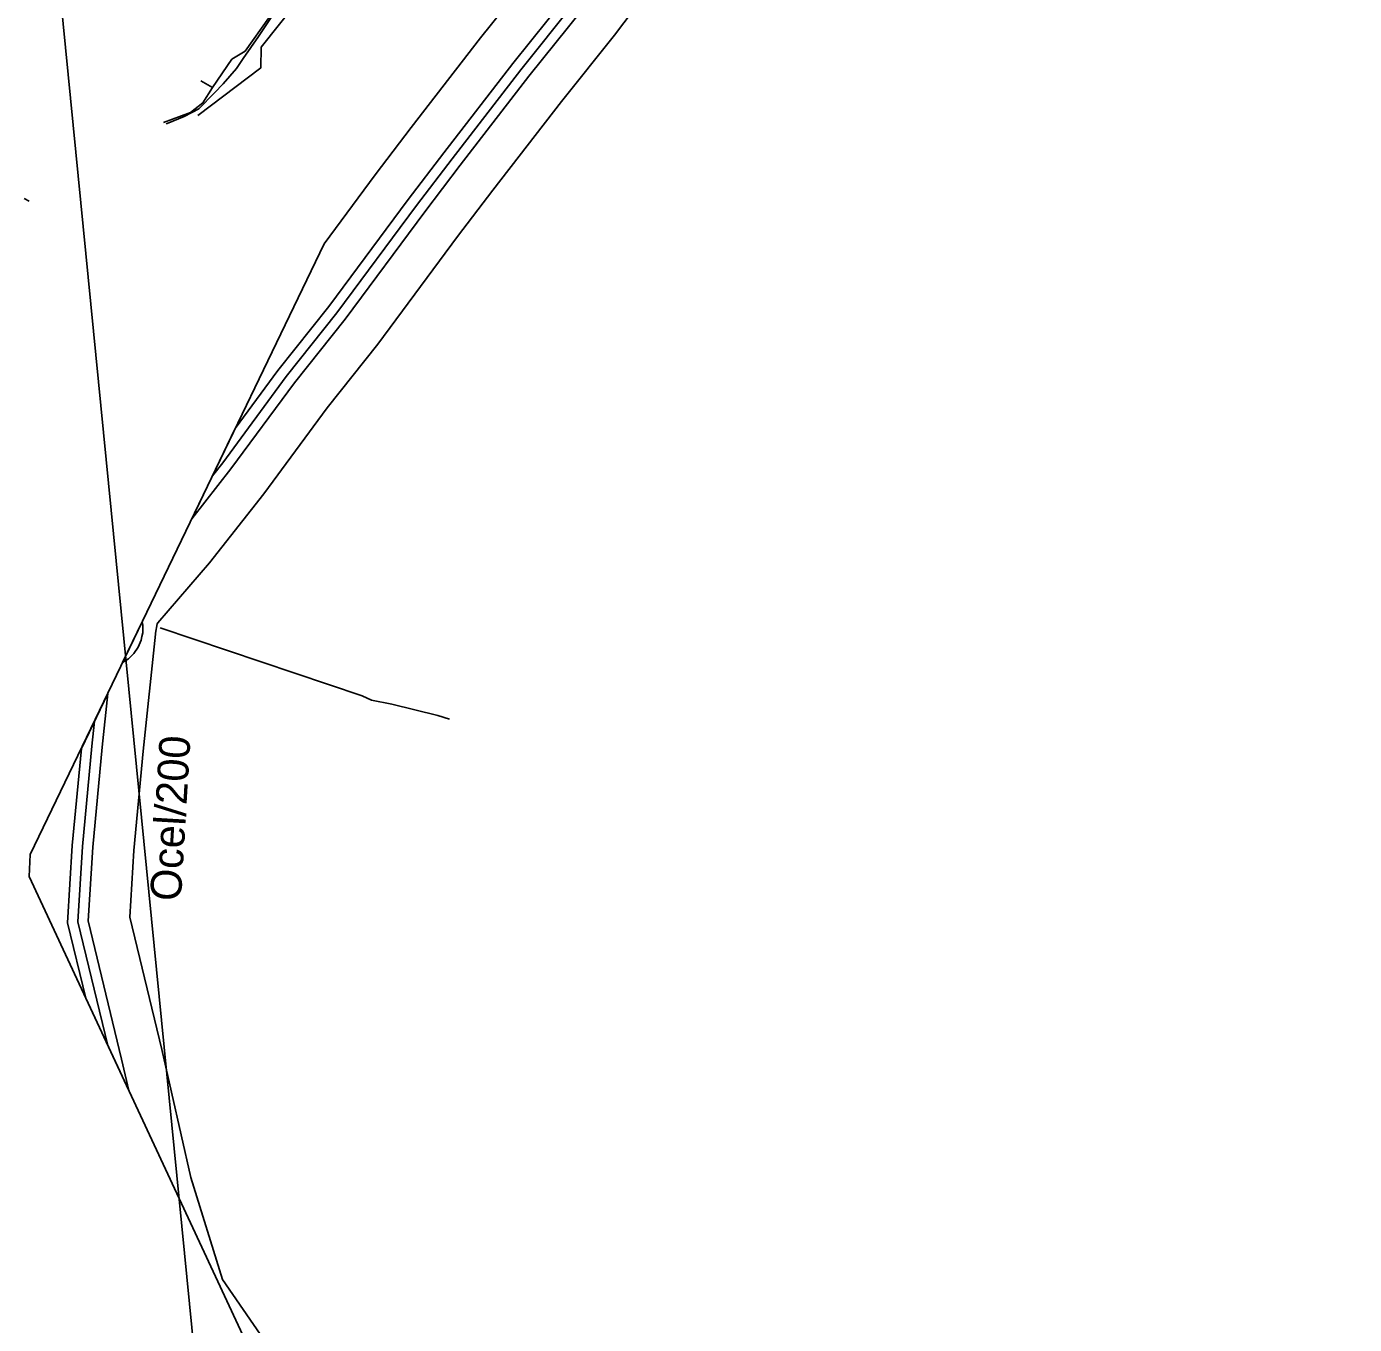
# Model space of a CAD drawing. Extents: x -555222 to -543220, y -1067119 to -1030889.
# Drawn here: x -550305 to -549789, y -1044176 to -1043672 of the extents above; entities that cross this region are included whole.
import ezdxf

# ---------------------------------------------------------------- set-up
doc = ezdxf.new("R2010")
doc.units = 0
for name, color, linetype in [('07_ELEKTRO', 7, 'Continuous'), ('07_OCH_P A POPISY TI', 7, 'Continuous'), ('07_PLYNOVOD', 7, 'Continuous'), ('07_SDĚLOVACÍ', 7, 'Continuous')]:
    doc.layers.add(name, color=color, linetype=linetype)

msp = doc.modelspace()

# ---------------------------------------------------------------- linework, layer by layer
at = {"layer": '07_ELEKTRO'}
msp.add_lwpolyline([(-550238.32, -1043706.58), (-550213.9, -1043688.03), (-550213.72, -1043680.02), (-550198.94, -1043661.37), (-550169.12, -1043629.26), (-550146.86, -1043607.87), (-550127.82, -1043567.81), (-550120.72, -1043555.47), (-550105.91, -1043534.57)], dxfattribs=at)
at = {"layer": '07_OCH_P A POPISY TI'}
for p, q in [((-550047.59, -1043636.94), (-550076.57, -1043675.35)), ((-550128.66, -1043676.39), (-550108.15, -1043650.79)), ((-550116.08, -1043686.28), (-550095.52, -1043660.62)), ((-550089.2, -1043665.52), (-550109.78, -1043691.22)), ((-550076.57, -1043675.35), (-550097.2, -1043701.11)), ((-550155.5, -1043711.23), (-550128.66, -1043676.39)), ((-550142.8, -1043720.97), (-550116.08, -1043686.28)), ((-550109.78, -1043691.22), (-550136.46, -1043725.83)), ((-550097.2, -1043701.11), (-550123.76, -1043735.57)), ((-550169.44, -1043729.5), (-550155.5, -1043711.23)), ((-550156.66, -1043739.12), (-550142.8, -1043720.97)), ((-550136.46, -1043725.83), (-550150.26, -1043743.92)), ((-550189.34, -1043756.35), (-550169.44, -1043729.5)), ((-550123.76, -1043735.57), (-550137.48, -1043753.54)), ((-550187.47, -1043780.7), (-550156.66, -1043739.12)), ((-550150.26, -1043743.92), (-550181.13, -1043785.58)), ((-550303.33, -1043993.45), (-550189.34, -1043756.35)), ((-550137.48, -1043753.54), (-550168.44, -1043795.33)), ((-550207.2, -1043805.46), (-550187.47, -1043780.7)), ((-550181.13, -1043785.58), (-550200.84, -1043810.32)), ((-550168.44, -1043795.33), (-550188.14, -1043820.05)), ((-550223.79, -1043828), (-550207.2, -1043805.46)), ((-550200.84, -1043810.32), (-550225.45, -1043843.75)), ((-550188.14, -1043820.05), (-550212.71, -1043853.45)), ((-550240.64, -1043863.05), (-550223.79, -1043828)), ((-550225.45, -1043843.75), (-550240.64, -1043863.05)), ((-550212.71, -1043853.45), (-550233.79, -1043880.22)), ((-550233.79, -1043880.22), (-550253.77, -1043903.48)), ((-550267.48, -1043918.87), (-550259.88, -1043903.06)), ((-550259.67, -1043907.35), (-550259.98, -1043908.79)), ((-550259.88, -1043903.06), (-550259.63, -1043904.39)), ((-550259.63, -1043904.39), (-550259.67, -1043907.35)), ((-550254.78, -1043907.92), (-550259.52, -1043953.35)), ((-550254.72, -1043907.49), (-550254.78, -1043907.92)), ((-550254.06, -1043903.88), (-550254.72, -1043907.49)), ((-550253.77, -1043903.48), (-550254.06, -1043903.88)), ((-550261.46, -1043912.95), (-550263.14, -1043915.38)), ((-550260.29, -1043910.24), (-550261.46, -1043912.95)), ((-550259.98, -1043908.79), (-550260.29, -1043910.24)), ((-550265.26, -1043917.44), (-550267.48, -1043918.87)), ((-550263.14, -1043915.38), (-550265.26, -1043917.44)), ((-550283.52, -1043952.24), (-550273.26, -1043930.91)), ((-550273.26, -1043930.91), (-550275.44, -1043951.77)), ((-550287.1, -1043989.99), (-550283.52, -1043952.24)), ((-550275.44, -1043951.77), (-550279.12, -1043990.61)), ((-550259.52, -1043953.35), (-550263.17, -1043991.83)), ((-550288.87, -1044019.92), (-550287.1, -1043989.99)), ((-550303.83, -1044001.93), (-550303.33, -1043993.45)), ((-550279.12, -1043990.61), (-550280.81, -1044019.2)), ((-550263.17, -1043991.83), (-550264.7, -1044017.77)), ((-550160.95, -1044308.6), (-550303.83, -1044001.93)), ((-550281.8, -1044049.21), (-550288.87, -1044019.92)), ((-550280.81, -1044019.2), (-550267.88, -1044072.83)), ((-550264.7, -1044017.77), (-550252.29, -1044069.19)), ((-550265.13, -1044085), (-550281.8, -1044049.21)), ((-550267.88, -1044072.83), (-550265.13, -1044085)), ((-550252.29, -1044069.19), (-550241.08, -1044118.86)), ((-550241.08, -1044118.86), (-550228.72, -1044158.37)), ((-550228.72, -1044158.37), (-550196.82, -1044204.77))]:
    msp.add_line(p, q, dxfattribs=at)
at = {"layer": '07_PLYNOVOD'}
for points in [[(-550232.65, -1043846.44), (-550228.63, -1043841.33), (-550204.02, -1043807.89), (-550184.3, -1043783.14), (-550153.46, -1043741.52), (-550139.63, -1043723.4), (-550112.93, -1043688.75), (-550092.36, -1043663.07)], [(-550250.55, -1043709.8), (-550250.18, -1043709.61), (-550243.64, -1043706.87), (-550237.9, -1043703.94), (-550231.85, -1043697.72), (-550228.53, -1043694.19), (-550223.34, -1043688.24), (-550220.65, -1043684.42), (-550214.77, -1043675.9), (-550209.13, -1043667.34)], [(-550273.27, -1044067.53), (-550284.84, -1044019.56), (-550283.11, -1043990.3), (-550279.42, -1043951.37), (-550278.4, -1043941.6)]]:
    msp.add_lwpolyline(points, dxfattribs=at)
at = {"layer": '07_SDĚLOVACÍ'}
for p, q in [((-550531.78, -1041228.78), (-549789.42, -1048745)), ((-550252.96, -1043905.46), (-550174.53, -1043931.82)), ((-550174.53, -1043931.82), (-550170.88, -1043933.55)), ((-550170.88, -1043933.55), (-550163.07, -1043935.05)), ((-550163.07, -1043935.05), (-550145.17, -1043939.51)), ((-550145.17, -1043939.51), (-550140.69, -1043940.88))]:
    msp.add_line(p, q, dxfattribs=at)
for points in [[(-550199.87, -1043652.46), (-550207.52, -1043663.59), (-550210.8, -1043668.62), (-550219.9, -1043681.54), (-550225.07, -1043684.67), (-550232.65, -1043695.7)], [(-550232.65, -1043695.7), (-550236.38, -1043701.65), (-550241.11, -1043705.37), (-550251.6, -1043709.25)], [(-550232.65, -1043695.7), (-550237.08, -1043693.02)], [(-550305.73, -1043738.76), (-550303.71, -1043739.72)]]:
    msp.add_lwpolyline(points, dxfattribs=at)

# ---------------------------------------------------------------- texts
at = {"layer": '07_OCH_P A POPISY TI'}
msp.add_text('Ocel/200', height=12, rotation=86.6163, dxfattribs=at).set_placement((-550244.91, -1044011.74))

doc.saveas('drawing.dxf')
